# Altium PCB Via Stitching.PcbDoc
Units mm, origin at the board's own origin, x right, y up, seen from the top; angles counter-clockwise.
Board outline 80.01 x 48.01 mm, 2 copper layers (Top Layer, Bottom Layer); 52 components, 54 nets, 192 pads, 149 vias.
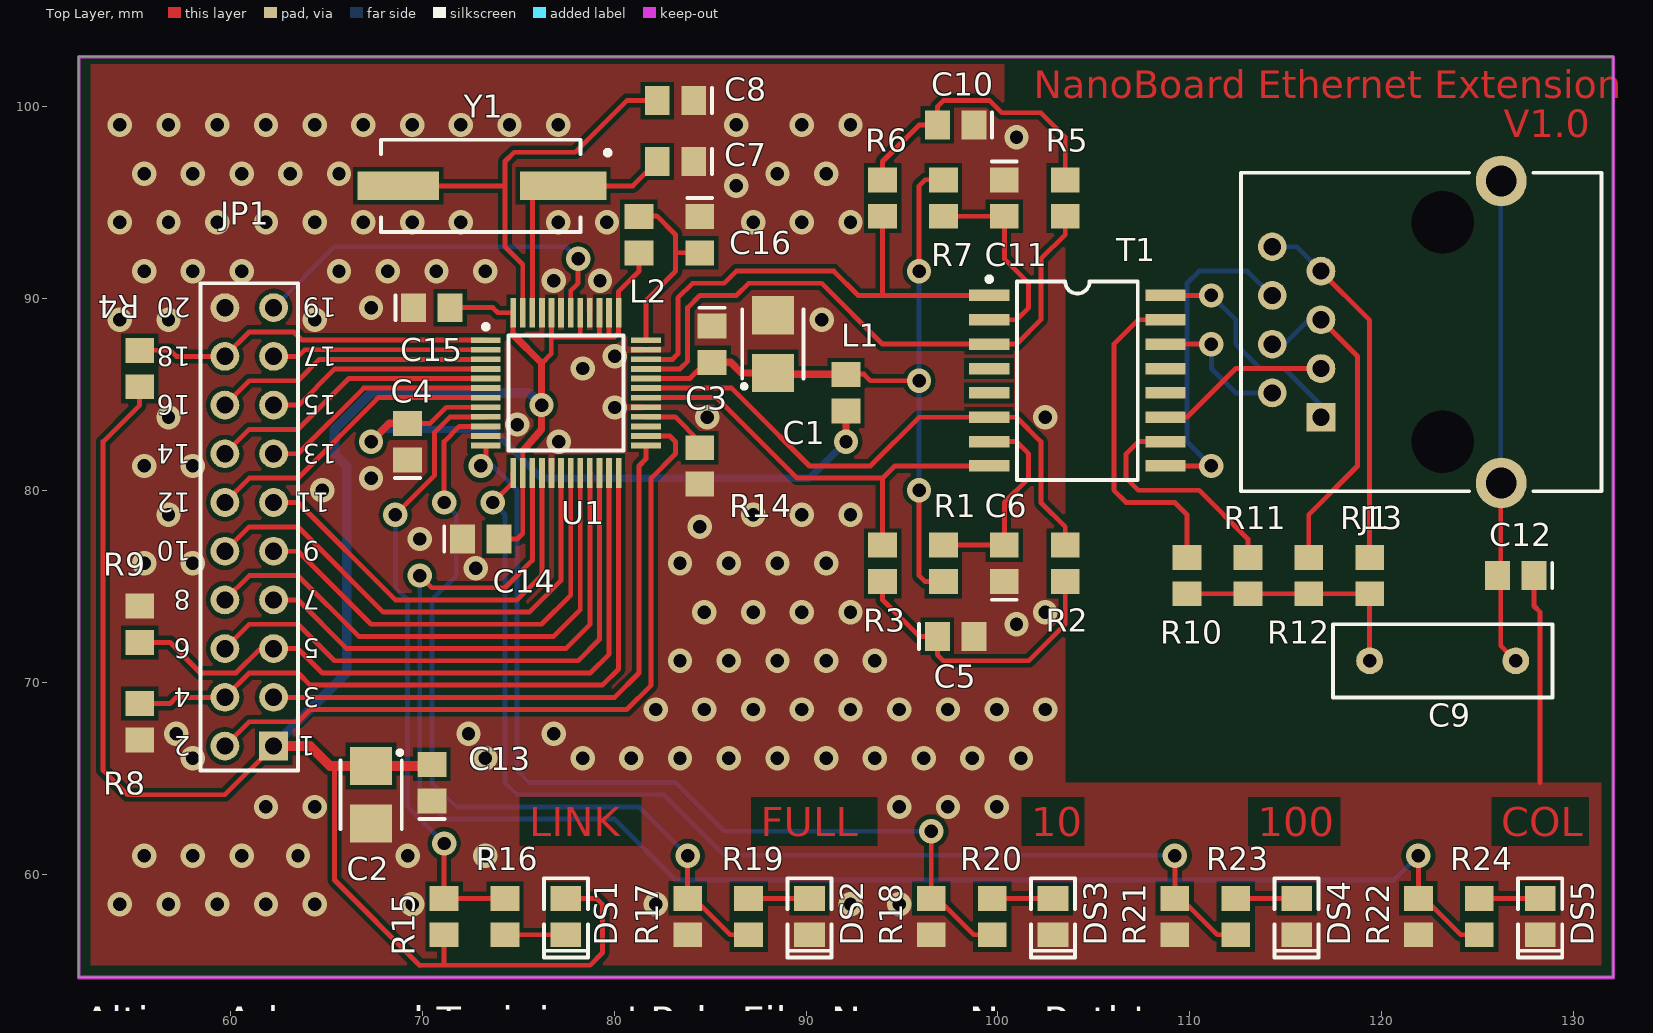
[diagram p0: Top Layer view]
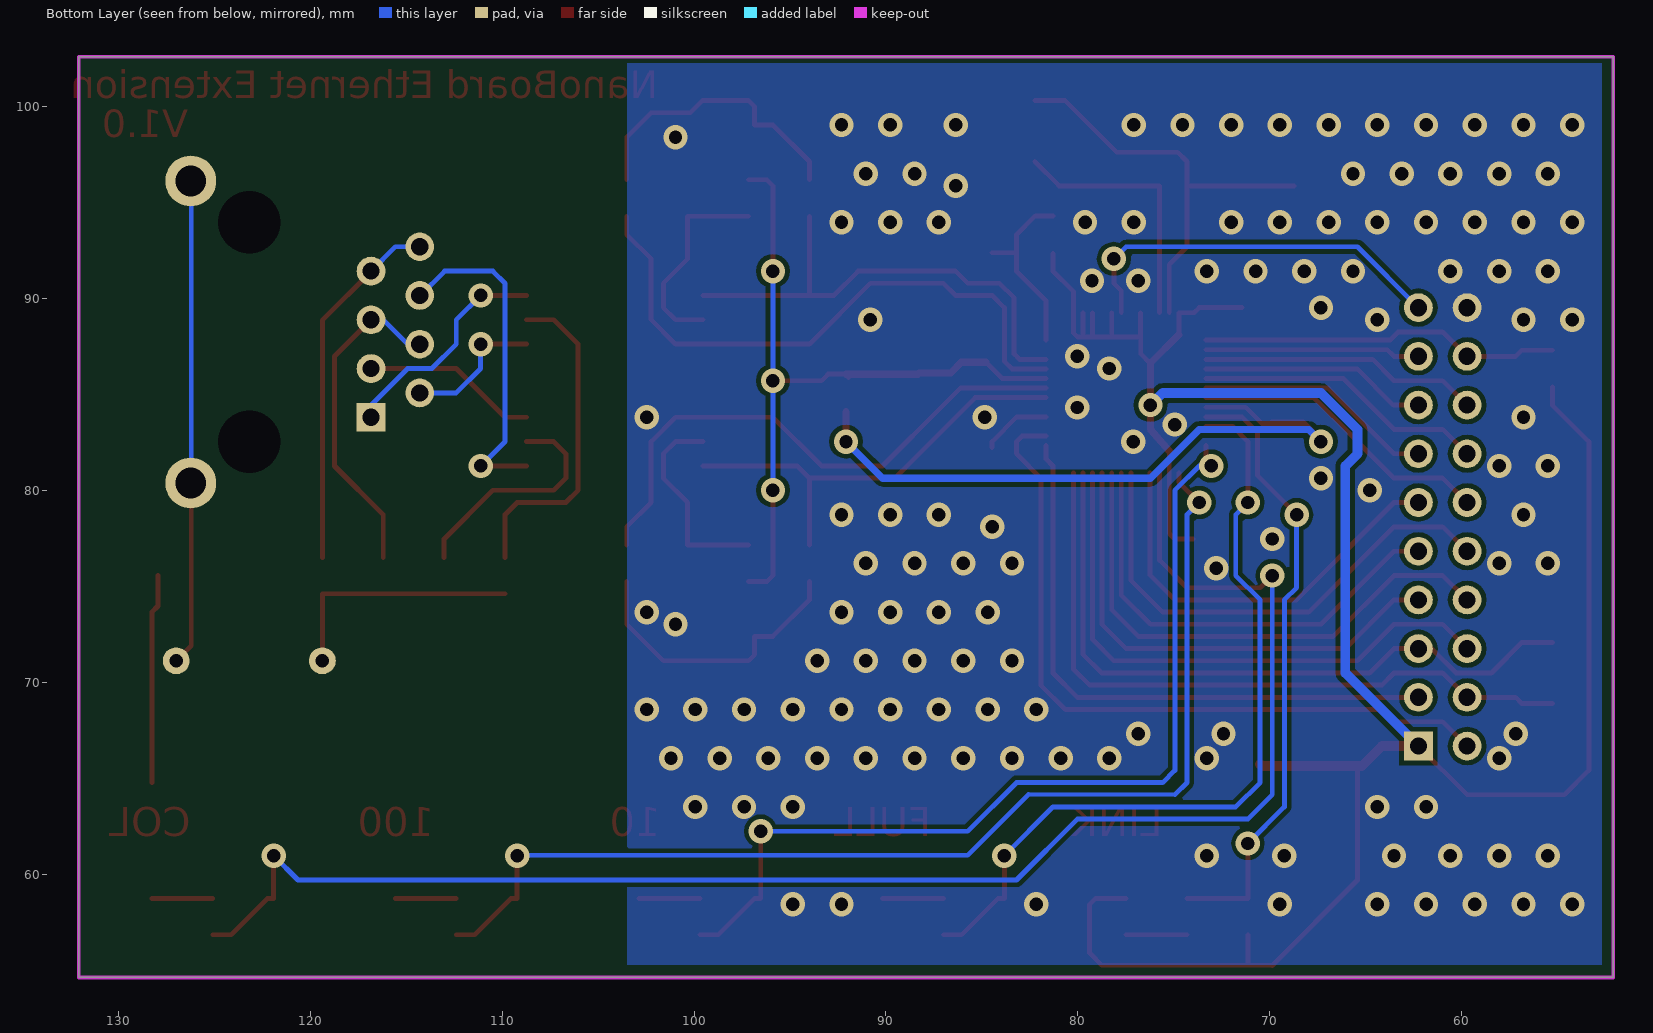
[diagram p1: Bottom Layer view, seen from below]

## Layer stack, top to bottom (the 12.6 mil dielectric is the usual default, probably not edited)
Top Solder: solder mask 0.0102, Solder Resist, Dk 3.5
Top Layer: signal copper 0.0356
Dielectric1: dielectric 0.32, FR-4, Dk 4.8
Bottom Layer: signal copper 0.0356
Bottom Solder: solder mask 0.0102, Solder Resist, Dk 3.5

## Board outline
52.07,54.61 52.07,102.616 132.08,102.616 132.08,54.61

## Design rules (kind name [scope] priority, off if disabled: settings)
Clearance Clearance_1 [(HasFootprint('TSQFP50P900X900-48'))] p1: gap=0.2 ignorepadtopadclearanceinfootprint=FALSE except(0: Arc-Hole Track-Hole SMDPad-Hole THPad-Hole Via-Hole Fill-Hole Poly-Hole Region-Hole Text-Hole)
Clearance [All] p2: gap=0.24 ignorepadtopadclearanceinfootprint=FALSE except(0: Arc-Hole Track-Hole SMDPad-Hole THPad-Hole Via-Hole Fill-Hole Poly-Hole Region-Hole Text-Hole)
FabricationTestPointUsage TestPointUsage [All] p1 off: valid=0 allowmultiple=FALSE
FabricationTestpoint Testpoint [All] p1 off: side=3 testpointundercomponent=TRUE minsize=1.016 maxsize=2.54 preferedsize=1.524 minholesize=0 maxholesize=1.016 preferedholesize=0.813 testpointgrid=0.025 allowsidetop=TRUE allowsidebottom=TRUE usegrid=TRUE gridtolerance=0
HoleSize [All] p1: absolutevalues=TRUE maxlimit=3.5 minlimit=0.025 maxpercent=80.000 minpercent=20.000
PolygonConnect [All] p1: connectstyle=Direct reliefconductorwidth=0.254 reliefentries=4 polygonreliefangle="90 Angle" airgapwidth=0.254
RoomDefinition PHY [InComponentClass('PHY')] p1: confinementstyle=ConfineIn formatcopy=TRUE lockcomponents=FALSE outline 52.07,54.61 132.08,54.61 132.08,102.87 52.07,102.87
RoutingVias [All] p1: holewidth=0.7 width=1.27 viastyle="Through Hole" minholewidth=0.7 minwidth=1.27 maxholewidth=0.7 maxwidth=1.27
SilkToSolderMaskClearance SilkscreenOverComponentPads [IsPad] p1: minsilkscreentomaskgap=0.254 clearancetoexposedcopper=TRUE
SolderMaskExpansion [All] p1: expansion=0.102 istentingtop=FALSE
Width Width_1 [(InNet('3V3') OR InNet('GND') OR InNet('PWFBIN') OR InNet('PWFBOUT'))] p1: maxlimit=0.508 minlimit=0.127 preferedwidth=0.254
Width [All] p2: maxlimit=0.254 minlimit=0.254 preferedwidth=0.254
26 further rules are at their usual default settings.

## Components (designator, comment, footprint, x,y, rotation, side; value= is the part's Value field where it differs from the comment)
C1 "22uF 10V" CAPC3528 88.265,87.63 r90 top
C2 "22uF 10V" CAPC3528 67.31,64.135 r270 top
C3 "100nF 50V" CAPC2012 85.09,87.63 r270 top
C4 "100nF 50V" CAPC2012 69.215,82.55 r90 top
C5 "100nF 50V" CAPC2012 97.79,72.39 r0 top
C6 "100nF 50V" CAPC2012 100.33,76.2 r90 top
C7 "20pF 50V" CAPC2012 83.185,97.155 r180 top
C8 "20pF 50V" CAPC2012 83.185,100.33 r180 top
C9 "100pF 3KV" CAPR7_5-3_6x7_5 123.19,71.12 r0 top
C10 "100nF 50V" CAPC2012 97.79,99.06 r180 top
C11 "100nF 50V" CAPC2012 100.33,95.25 r270 top
C12 "100nF 50V" CAPC2012 127,75.565 r180 top
C13 "100nF 50V" CAPC2012 70.485,64.77 r90 top
C14 "100nF 50V" CAPC2012 73.025,77.47 r0 top
C15 "100nF 50V" CAPC2012 70.485,89.535 r0 top
C16 "100nF 50V" CAPC2012 84.455,93.345 r270 top
DS1 "RED" LED2013 77.47,57.785 r90 top
DS2 "RED" LED2013 90.17,57.785 r90 top
DS3 "RED" LED2013 102.87,57.785 r90 top
DS4 "RED" LED2013 115.57,57.785 r90 top
DS5 "RED" LED2013 128.27,57.785 r90 top
J1 "RJ45 HEADER" 95122-2881 120.27,88.265 r90 top
JP1 "2x10 HEADER" HDR2X10 62.23,66.675 r90 top
L1 "30R@100MHz 600mA" INDC2012 92.075,85.09 r270 top
L2 "30R@100MHz 600mA" INDC2012 81.28,93.345 r90 top
R1 "0R 5%" RESC2012 97.155,76.2 r270 top
R2 "50R 1%" RESC2012 103.505,76.2 r270 top
R3 "50R 1%" RESC2012 93.98,76.2 r270 top
R4 "5K1 5%" RESC2012 55.245,86.36 r270 top
R5 "50R 1%" RESC2012 103.505,95.25 r270 top
R6 "50R 1%" RESC2012 93.98,95.25 r270 top
R7 "0R 5%" RESC2012 97.155,95.25 r90 top
R8 "5K1 5%" RESC2012 55.245,67.945 r90 top
R9 "5K1 5%" RESC2012 55.245,73.025 r270 top
R10 "75R 5%" RESC2012 109.855,75.565 r90 top
R11 "75R 5%" RESC2012 113.03,75.565 r90 top
R12 "75R 5%" RESC2012 116.205,75.565 r90 top
R13 "75R 5%" RESC2012 119.38,75.565 r90 top
R14 "2K 1%" RESC2012 84.455,81.28 r90 top
R15 "5K1 5%" RESC2012 71.12,57.785 r270 top
R16 "510R 5%" RESC2012 74.295,57.785 r270 top
R17 "5K1 5%" RESC2012 83.82,57.785 r90 top
R18 "5K1 5%" RESC2012 96.52,57.785 r270 top
R19 "510R 5%" RESC2012 86.995,57.785 r90 top
R20 "510R 5%" RESC2012 99.695,57.785 r90 top
R21 "5K1 5%" RESC2012 109.22,57.785 r90 top
R22 "5K1 5%" RESC2012 121.92,57.785 r270 top
R23 "510R 5%" RESC2012 112.395,57.785 r90 top
R24 "510R 5%" RESC2012 125.095,57.785 r90 top
T1 "TS6121C" SOIC127P910-16 104.14,85.725 r270 top
U1 "RTL8201CL" TSQFP50P900X900-48 77.47,85.09 r0 top
Y1 "25MHz" "XTAL_HC49SMD 20Mhz  +/-30ppm 20pf" 73.025,95.885 r180 top

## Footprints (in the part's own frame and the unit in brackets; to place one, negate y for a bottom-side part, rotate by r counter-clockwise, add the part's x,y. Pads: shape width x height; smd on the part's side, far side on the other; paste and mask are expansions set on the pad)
95122-2881 [mm]
  rect 1.5x1.5 hole 0.9: 1(-4.445,3.43)
  round 1.5 hole 0.9: 2(-3.175,5.97) 3(-1.905,3.43) 4(-0.635,5.97) 5(0.635,3.43) 6(1.905,5.97) 7(3.175,3.43) 8(4.445,5.97)
  round 2.65 hole 1.6: MH1(-7.875,-5.97) MH2(7.875,-5.97)
  round 2.95 hole 3.25 unplated: MH3(-5.715,-2.92) MH4(5.715,-2.92)
  silkscreen extent -8.3,-11.2 8.3,7.6
CAPC2012 [mm]
  rect 1.3x1.5 smd: 1(-0.95,0) 2(0.95,0)
  silkscreen extent -1.9,-0.65 -1.9,0.65
CAPC3528 [mm]
  rect 2x2.2 smd: 1(-1.5,0) 2(1.5,0)
  silkscreen extent -2.3,-1.6 1.8,1.6
CAPR7_5-3_6x7_5 [mm]
  round 1.4 hole 0.7: 1(-3.81,0) 2(3.81,0)
  silkscreen extent -5.71,-1.91 5.71,1.91
HDR2X10 [mm]
  rect 1.5x1.5 hole 0.9: 1(0,0)
  round 1.5 hole 0.9: 2(0,2.54) 3(2.54,0) 4(2.54,2.54) 5(5.08,0) 6(5.08,2.54) 7(7.62,0) 8(7.62,2.54) 9(10.16,0) 10(10.16,2.54) 11(12.7,0) 12(12.7,2.54) 13(15.24,0) 14(15.24,2.54) 15(17.78,0) 16(17.78,2.54) 17(20.32,0) 18(20.32,2.54) 19(22.86,0) 20(22.86,2.54)
  silkscreen extent -1.27,-1.27 24.13,3.81, body extent -1.37,-1.37 24.23,3.91, height 3.2
INDC2012 [mm]
  rect 1.3x1.5 smd: 1(-0.95,0) 2(0.95,0)
LED2013 [mm]
  rect 1.3x1.6 smd: 1(0.95,0) 2(-0.95,0)
  silkscreen extent -2.13,-1.15 2,1.15
RESC2012 [mm]
  rect 1.3x1.5 smd: 1(-0.95,0) 2(0.95,0)
SOIC127P910-16 [mm]
  rect 0.6x2.1 smd: 1(-4.445,-4.6) 2(-3.175,-4.6) 3(-1.905,-4.6) 4(-0.635,-4.6) 5(0.635,-4.6) 6(1.905,-4.6) 7(3.175,-4.6) 8(4.445,-4.6) 9(4.445,4.6) 10(3.175,4.6) 11(1.905,4.6) 12(0.635,4.6) 13(-0.635,4.6) 14(-1.905,4.6) 15(-3.175,4.6) 16(-4.445,4.6)
  silkscreen extent -5.42,-4.72 5.17,3.15
TSQFP50P900X900-48 [mm]
  rect 1.55x0.3 smd: 1(-4.175,2.75) 2(-4.175,2.25) 3(-4.175,1.75) 4(-4.175,1.25) 5(-4.175,0.75) 6(-4.175,0.25) 7(-4.175,-0.25) 8(-4.175,-0.75) 9(-4.175,-1.25) 10(-4.175,-1.75) 11(-4.175,-2.25) 12(-4.175,-2.75) 25(4.175,-2.75) 26(4.175,-2.25) 27(4.175,-1.75) 28(4.175,-1.25) 29(4.175,-0.75) 30(4.175,-0.25) 31(4.175,0.25) 32(4.175,0.75) 33(4.175,1.25) 34(4.175,1.75) 35(4.175,2.25) 36(4.175,2.75)
  rect 0.3x1.55 smd: 13(-2.75,-4.175) 14(-2.25,-4.175) 15(-1.75,-4.175) 16(-1.25,-4.175) 17(-0.75,-4.175) 18(-0.25,-4.175) 19(0.25,-4.175) 20(0.75,-4.175) 21(1.25,-4.175) 22(1.75,-4.175) 23(2.25,-4.175) 24(2.75,-4.175) 37(2.75,4.175) 38(2.25,4.175) 39(1.75,4.175) 40(1.25,4.175) 41(0.75,4.175) 42(0.25,4.175) 43(-0.25,4.175) 44(-0.75,4.175) 45(-1.25,4.175) 46(-1.75,4.175) 47(-2.25,4.175) 48(-2.75,4.175)
  silkscreen extent -4.3,-3 3,3.57, body extent -3,-3 3,3, height 1.7
"XTAL_HC49SMD 20Mhz  +/-30ppm 20pf" [mm]
  rect 4.5x1.5 smd: 1(-4.3,0)
  rect 4.25x1.5 smd: 2(4.3,0)
  silkscreen extent -6.75,-2.4 5.2,2.4

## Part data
C1 C2: library part "Cap Pol1", "Polarized Capacitor (Radial)"
C3 C4 C5 C6 C7 C8 C9 C10 C11 C12 C13 C14 C15 C16: library part Cap, "Capacitor"
DS1 DS2 DS3 DS4 DS5: library part LED3, "Fairchild LED RED"
J1: library part 95122-2881, "Right Angle, Standard Profile, External Shield PCB Jack"
JP1: library part "Header 10X2", "Header, 10-Pin, Dual row"
L1 L2: library part Inductor, "Inductor Ferroxcube"
R1 R2 R3 R4 R5 R6 R7 R8 R9 R10 R11 R12 R13 R14 R15 R16 R17 R18 R19 R20 R21 R22 R23 R24: library part Res2, "Resistor"
T1: "Bothhand 10/100 BaseT Pulse Transformer"
U1: "Realtek Ethernet PHY tranceiver"
Y1: library part XTAL, "Crystal Oscillator"

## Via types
v1: diameter 1.27, hole 0.7, Top Layer to Bottom Layer, 149 vias

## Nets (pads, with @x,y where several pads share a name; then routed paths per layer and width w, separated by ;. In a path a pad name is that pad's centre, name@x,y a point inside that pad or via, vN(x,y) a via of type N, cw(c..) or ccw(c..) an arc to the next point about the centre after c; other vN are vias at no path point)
3V3: C2.1 C13.2 C14.2 C15.2 DS1.1 JP1.1 L2.1 R4.2 R15.2 U1.14 U1.37 U1.38 U1.39 U1.41 U1.44 U1.48 | length 130.3
  Top Layer w0.254: R4.2 55.245,84.455 53.34,82.55 53.34,65.405 54.61,64.135 59.69,64.135 JP1.1 ; 65.405,65.635 65.405,59.69 69.85,55.235 78.74,55.245 79.37,55.885 79.37,58.42 79.055,58.735 DS1.1 ; 71.12,55.255 R15.2 ; C15.2 73.66,89.535 73.93,89.265 U1.48 74.72,88.124 ; C14.2 74.93,77.47 75.22,77.76 U1.14 75.22,82.056 ; 76.2,86.614 76.708,87.122 76.708,88.011 80.01,88.011 80.22,88.221 80.22,90.38 81.28,91.44 L2.1@81.28,92.37 ; 76.72,88.023 U1.44 ; 78.22,88.023 U1.41 ; 79.22,88.039 U1.39 ; 79.72,88.047 U1.38
  Top Layer w0.381: 74.72,88.124 76.2,86.644 76.2,83.185 75.22,82.056
  Top Layer w0.508: JP1.1 64.135,66.675 65.175,65.635 70.4,65.635 C13.2
  Bottom Layer w0.508: JP1.1 66.04,70.485 66.04,81.28 65.405,81.915 65.405,83.185 67.31,85.09 75.565,85.09 v1(76.2,84.455)
3V3A: C16.2 L2.2 U1.36 | length 9.7
  Top Layer w0.254: L2.2@81.28,94.32 82.21,94.32 83.185,93.345 83.185,91.44 81.645,89.9 U1.36 ; 83.19,92.395 C16.2
COL: JP1.18 R4.1 U1.1 | length 18.9
  Top Layer w0.254: R4.1@55.245,87.315 56.83,87.315 57.15,86.995 JP1.18 60.96,88.265 63.285,88.265 63.71,87.84 U1.1
CRS: JP1.5 R9.2 U1.23 | length 36
  Top Layer w0.254: R9.2 56.83,72.075 58.42,70.485 60.261,70.485 61.531,71.755 JP1.5 63.5,71.755 64.77,70.485 78.74,70.485 79.72,71.465 U1.23
GND: C1.2 C2.2 C3.1 C4.1 C5.2 C6.1 C7.1 C8.1 C10.1 C11.1 C12.1 C13.1 C14.1 C15.1 C16.1 DS2.2 DS3.2 DS4.2 DS5.2 JP1.20 R8.1 R9.1 R14.1 R17.1 R18.2 R21.1 R22.2 U1.11 U1.17 U1.29 U1.35 U1.40 U1.43 U1.45 | length 10.9
  Top Layer w0.254: C12.1 127.95,73.98 128.27,73.66 128.27,64.77
  other v1: 54.21,58.42 56.75,58.42 59.29,58.42 61.83,58.42 64.37,58.42 69.45,58.42 82.15,58.42 92.31,58.42 94.85,58.42 55.48,60.96 58.02,60.96 60.56,60.96 63.5,60.96 69.215,60.96 73.26,60.96 61.83,63.5 64.37,63.5 94.85,63.5 97.39,63.5 99.93,63.5 58.02,66.04 73.26,66.04 78.34,66.04 80.88,66.04 83.42,66.04 85.96,66.04 88.5,66.04 91.04,66.04 93.58,66.04 96.12,66.04 98.66,66.04 101.2,66.04 57.15,67.31 72.39,67.31 76.835,67.31 82.15,68.58 84.69,68.58 87.23,68.58 89.77,68.58 92.31,68.58 94.85,68.58 97.39,68.58 99.93,68.58 102.47,68.58 83.42,71.12 85.96,71.12 88.5,71.12 91.04,71.12 93.58,71.12 100.965,73.025 84.69,73.66 87.23,73.66 89.77,73.66 92.31,73.66 102.47,73.66 72.771,75.946 55.48,76.2 58.02,76.2 83.42,76.2 85.96,76.2 88.5,76.2 91.04,76.2 69.85,77.47 84.455,78.105 56.75,78.74 87.23,78.74 89.77,78.74 92.31,78.74 64.77,80.01 67.31,80.645 55.48,81.28 58.02,81.28 77.089,82.55 74.93,83.439 56.75,83.82 84.836,83.82 102.47,83.82 80.01,84.328 78.34,86.36 80.01,86.995 54.21,88.9 56.75,88.9 64.37,88.9 90.805,88.9 67.31,89.535 76.835,90.932 79.248,90.932 55.48,91.44 58.02,91.44 60.56,91.44 65.64,91.44 68.18,91.44 70.72,91.44 73.26,91.44 54.21,93.98 56.75,93.98 59.29,93.98 61.83,93.98 64.37,93.98 66.91,93.98 69.45,93.98 71.99,93.98 77.07,93.98 79.61,93.98 87.23,93.98 89.77,93.98 92.31,93.98 86.36,95.885 55.48,96.52 58.02,96.52 60.56,96.52 63.1,96.52 65.64,96.52 88.5,96.52 91.04,96.52 100.965,98.425 54.21,99.06 56.75,99.06 59.29,99.06 61.83,99.06 64.37,99.06 66.91,99.06 69.45,99.06 71.99,99.06 74.53,99.06 77.07,99.06 86.36,99.06 89.77,99.06 92.31,99.06
LED0: R15.1 R16.1 U1.9 | length 32.4
  Top Layer w0.254: v1(68.58,78.74) 70.628,80.788 70.628,83.034 71.434,83.84 U1.9 ; v1(71.12,61.595) R15.1 R16.1
  Bottom Layer w0.254: v1(68.58,78.74) 68.58,74.93 69.215,74.295 69.215,63.5 v1(71.12,61.595)
LED1: R17.2 R19.1 U1.10 | length 42.2
  Top Layer w0.254: v1@71.122,79.377 71.122,82.552 71.91,83.34 U1.10 ; v1(83.82,60.96) R17.2 84.14,58.735 86.04,56.835 R19.1
  Bottom Layer w0.254: v1(71.12,79.375) 71.755,78.74 71.755,75.565 70.485,74.295 70.485,64.77 71.755,63.5 81.28,63.5 v1(83.82,60.96)
LED2: R18.1 R20.1 U1.12 | length 48.6
  Top Layer w0.254: v1(73.025,81.28) 73.295,81.55 U1.12 ; v1(96.52,62.23) R18.1 96.835,58.735 98.735,56.835 R20.1
  Bottom Layer w0.254: v1(73.025,81.28) 73.66,81.28 74.93,80.01 74.93,65.405 75.565,64.77 83.185,64.77 85.725,62.23 v1(96.52,62.23)
LED3: R21.2 R23.1 U1.13 | length 59.5
  Top Layer w0.254: v1(73.66,79.375) 74.72,80.435 U1.13 ; v1(109.22,60.96) R21.2 109.54,58.735 111.44,56.835 R23.1
  Bottom Layer w0.254: v1(73.66,79.375) 74.295,78.74 74.295,64.77 74.93,64.135 82.55,64.163 85.725,60.988 v1(109.22,60.96)
LED4: R22.1 R24.1 U1.15 | length 83.3
  Top Layer w0.254: v1(69.85,75.565) 70.485,74.93 74.295,74.93 75.72,76.355 U1.15 ; v1(121.92,60.96) R22.1 122.235,58.735 124.135,56.835 R24.1
  Bottom Layer w0.254: v1(69.85,75.565) 69.85,64.135 71.12,62.865 80.01,62.865 83.185,59.69 120.65,59.69 v1(121.92,60.96)
MDC: JP1.3 U1.25 | length 31.6
  Top Layer w0.254: JP1.3 80.01,69.215 81.28,70.485 81.28,81.28 81.645,81.645 U1.25
MDIO: JP1.2 U1.26 | length 38.4
  Top Layer w0.254: JP1.2 60.96,67.945 63.5,67.945 64.135,68.58 80.645,68.58 81.915,69.85 81.915,80.645 83.185,81.915 83.185,82.55 82.895,82.84 U1.26
NetC5_1: C5.1 R2.2 R3.2 | length 15.4
  Top Layer w0.254: R3.2 93.98,74.295 95.885,72.39 C5.1 96.84,71.435 97.155,71.12 101.6,71.12 103.505,73.025 R2.2
NetC6_2: C6.2 R1.1 T1.7 | length 10.8
  Top Layer w0.254: R1.1 C6.2 100.33,79.375 101.6,80.645 101.6,81.915 100.965,82.55 T1.7
NetC7_2: C7.2 U1.46 Y1.1 | length 13.7
  Top Layer w0.254: U1.46 75.72,95.885 80.965,95.885 C7.2
NetC8_2: C8.2 U1.47 Y1.2 | length 23.1
  Top Layer w0.254: Y1.2 74.295,95.885 ; U1.47 75.22,91.785 74.295,92.71 74.295,97.155 74.775,97.635 77.95,97.635 80.645,100.33 C8.2
NetC9_1: C9.1 R10.1 R11.1 R12.1 R13.1 | length 13
  Top Layer w0.254: R10.1 R13.1 C9.1
NetC9_2: C9.2 C12.2 J1.MH1 J1.MH2 | length 25.3
  Top Layer w0.254: J1.MH1@126.215,80.39 126.215,71.905 C9.2
  Bottom Layer w0.254: J1.MH1@126.215,80.39 J1.MH2@126.215,96.14
NetC10_2: C10.2 R5.1 R6.1 | length 15.4
  Top Layer w0.254: R6.1 93.98,97.155 95.885,99.06 C10.2 96.84,100.015 97.155,100.33 99.568,100.33 100.203,99.695 102.235,99.695 103.505,98.425 R5.1
NetC11_2: C11.2 R7.1 T1.2 | length 10.8
  Top Layer w0.254: R7.1 C11.2 100.33,92.075 101.6,90.805 101.6,89.535 100.965,88.9 T1.2
NetDS1_2: DS1.2 R16.2 | length 3.2
  Top Layer w0.254: R16.2 DS1.2
NetDS2_1: DS2.1 R19.2 | length 3.2
  Top Layer w0.254: R19.2 DS2.1
NetDS3_1: DS3.1 R20.2 | length 3.2
  Top Layer w0.254: R20.2 DS3.1
NetDS4_1: DS4.1 R23.2 | length 3.2
  Top Layer w0.254: R23.2 DS4.1
NetDS5_1: DS5.1 R24.2 | length 3.2
  Top Layer w0.254: R24.2 DS5.1
NetJ1_1: J1.1 T1.16 | length 11.8
  Top Layer w0.254: T1.16 v1(111.125,90.17)
  Bottom Layer w0.254: v1(111.125,90.17) 112.395,88.9 112.395,87.63 113.665,86.36 114.935,86.36 116.815,84.48 J1.1@116.815,83.82
NetJ1_2: J1.2 T1.14 | length 7.3
  Top Layer w0.254: T1.14 v1(111.125,87.63)
  Bottom Layer w0.254: v1(111.125,87.63) 111.125,86.36 112.395,85.09 J1.2@114.275,85.09
NetJ1_3: J1.3 T1.11 | length 9.1
  Top Layer w0.254: T1.11 109.855,83.82 112.395,86.36 J1.3@116.815,86.36
NetJ1_4: J1.4 J1.5 R12.2 | length 16.7
  Top Layer w0.254: R12.2 116.205,78.74 118.745,81.28 118.745,86.995 J1.5
  Bottom Layer w0.254: J1.4@114.275,87.63 114.935,87.63 J1.5@116.205,88.9
NetJ1_6: J1.6 T1.9 | length 17.6
  Top Layer w0.254: T1.9 v1(111.125,81.28)
  Bottom Layer w0.254: v1(111.125,81.28) 109.855,82.55 109.855,90.805 110.49,91.44 113.005,91.44 J1.6@114.275,90.17
NetJ1_7: J1.7 J1.8 R13.2 | length 19
  Top Layer w0.254: J1.7@116.815,91.44 119.38,88.875 R13.2
  Bottom Layer w0.254: J1.8@114.275,92.71 115.57,92.71 J1.7@116.815,91.465
NetR2_1: R2.1 T1.6 U1.31 | length 29.8
  Top Layer w0.254: U1.31 86.11,85.34 86.995,84.455 90.17,81.28 93.345,81.28 95.885,83.82 T1.6 100.965,83.82 102.235,82.55 102.235,79.375 103.505,78.105 R2.1
NetR3_1: R3.1 T1.8 U1.30 | length 23.4
  Top Layer w0.254: U1.30 85.34,84.84 89.535,80.645 93.98,80.645 ; R3.1 93.98,80.645 ; T1.8 94.615,81.28 93.98,80.645
NetR5_2: R5.2 T1.3 U1.33 | length 31.8
  Top Layer w0.254: U1.33 83.419,86.34 83.82,86.741 83.82,89.535 84.455,90.17 86.36,90.17 86.995,90.805 90.805,90.805 93.98,87.63 T1.3 100.965,87.63 102.235,88.9 102.235,92.075 103.505,93.345 R5.2
NetR6_2: R6.2 T1.1 U1.34 | length 26.2
  Top Layer w0.254: U1.34 83.03,86.84 83.312,87.122 83.312,90.043 84.074,90.805 85.725,90.805 86.36,91.44 91.44,91.44 92.71,90.17 T1.1 ; 93.98,90.17 R6.2
NetR10_2: R10.2 T1.15 | length 17.4
  Top Layer w0.254: T1.15 107.315,88.9 106.045,87.63 106.045,80.01 106.68,79.375 109.22,79.375 109.855,78.74 R10.2
NetR11_2: R11.2 T1.10 | length 12.2
  Top Layer w0.254: T1.10 107.315,82.55 106.68,81.915 106.68,80.645 107.315,80.01 110.49,80.01 113.03,77.47 R11.2
NetR14_2: R14.2 U1.28 | length 3.7
  Top Layer w0.254: U1.28 83.165,83.84 84.455,82.55 R14.2
PWFBIN: C4.2 L1.2 U1.8 | length 35.2
  Top Layer w0.254: C4.2@69.85,83.5 70.395,83.5 71.235,84.34 U1.8
  Top Layer w0.381: v1(67.31,82.55) 68.26,83.5 C4.2@69.85,83.5 ; v1(92.075,82.55) L1.2@92.075,84.115
  Bottom Layer w0.381: v1(67.31,82.55) 67.945,83.185 73.66,83.185 76.2,80.645 90.17,80.645 v1(92.075,82.55)
PWFBOUT: C1.1 C3.2 L1.1 R1.2 R7.2 U1.32 | length 38.1
  Top Layer w0.254: U1.32 83.935,85.84 C3.2@84.775,86.68 ; C1.1 C1.1@88.33,86.065 ; L1.1@91.931,85.876 L1.1@91.948,85.893 ; L1.1@92.075,86.065 93.005,86.065 93.345,85.725 v1(95.885,85.725) ; v1(95.885,80.01) 95.885,75.565 96.2,75.25 R1.2 ; v1(95.885,91.44) 95.885,95.885 96.2,96.2 R7.2
  Top Layer w0.381: C3.2@84.775,86.68 86.066,86.68 86.616,86.13 C1.1 ; C1.1@88.33,86.065 L1.1@92.075,86.065
  Bottom Layer w0.254: v1(95.885,80.01) v1(95.885,91.44)
RESETB: JP1.19 U1.42 | length 20.4
  Top Layer w0.254: U1.42 77.72,90.42 78.105,90.805 v1(78.105,92.075)
  Bottom Layer w0.254: JP1.19 65.405,92.71 77.47,92.71 v1(78.105,92.075)
RXC: JP1.11 U1.16 | length 22
  Top Layer w0.254: JP1.11 63.5,79.375 68.58,74.295 74.93,74.295 76.22,75.585 U1.16
RXD0: JP1.7 U1.21 | length 26
  Top Layer w0.254: JP1.7 63.5,74.295 66.04,71.755 77.47,71.755 78.72,73.005 U1.21
RXD1: JP1.8 U1.20 | length 28.1
  Top Layer w0.254: JP1.8 60.96,75.565 63.5,75.565 66.675,72.39 76.835,72.39 78.22,73.775 U1.20
RXD2: JP1.9 U1.19 | length 24.1
  Top Layer w0.254: JP1.9 63.5,76.835 67.31,73.025 76.2,73.025 77.72,74.545 U1.19
RXD3: JP1.10 U1.18 | length 26.2
  Top Layer w0.254: JP1.10 60.96,78.105 63.5,78.105 67.945,73.66 75.565,73.66 77.22,75.315 U1.18
RXDV: JP1.6 U1.22 | length 30
  Top Layer w0.254: JP1.6 60.96,73.025 63.5,73.025 65.405,71.12 78.105,71.12 79.22,72.235 U1.22
RXER: JP1.4 R8.2 U1.24 | length 36.5
  Top Layer w0.254: R8.2 56.835,68.895 57.155,69.215 JP1.4 60.96,70.485 63.5,70.485 64.135,69.85 79.375,69.85 80.22,70.695 U1.24
TXC: JP1.12 U1.7 | length 15.9
  Top Layer w0.254: JP1.12 60.96,80.645 63.5,80.645 67.695,84.84 U1.7
TXD0: JP1.13 U1.6 | length 12.5
  Top Layer w0.254: JP1.13 63.5,81.915 66.925,85.34 U1.6
TXD1: JP1.14 U1.5 | length 15.2
  Top Layer w0.254: JP1.14 60.96,83.185 63.5,83.185 66.155,85.84 U1.5
TXD2: JP1.15 U1.4 | length 11.8
  Top Layer w0.254: JP1.15 63.54,84.455 65.425,86.34 U1.4
TXD3: JP1.16 U1.3 | length 14.6
  Top Layer w0.254: JP1.16 60.96,85.725 63.5,85.725 64.615,86.84 U1.3
TXEN: JP1.17 U1.2 | length 11.2
  Top Layer w0.254: JP1.17 63.5,86.995 63.845,87.34 U1.2
pads on no net: J1.MH3 J1.MH4 T1.4 T1.5 T1.12 T1.13 U1.27

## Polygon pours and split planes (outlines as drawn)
GND on Top Layer "Top Layer-GND" (solid, remove dead copper, pour order 1000): 52.705,102.235 100.33,102.235 100.33,99.695 102.87,99.695 103.505,99.06 103.505,64.77 131.445,64.77 131.445,55.245 52.705,55.245
GND on Bottom Layer "Bottom Layer-GND" (solid, remove dead copper, pour order 1001): 52.68,102.27 103.48,102.27 103.48,55.28 52.68,55.28

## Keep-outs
Keep-Out Layer:
  the board outline again, w0.2

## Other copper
Top Layer:
  text "NanoBoard Ethernet Extension" at 101.854,100.457 h1.45
  text "V1.0" at 126.365,98.425 h1.45
  text "LINK" at 75.565,61.976 h1.52
  text "FULL" at 87.63,61.976 h1.52
  text "10" at 101.727,61.976 h1.52
  text "100" at 113.538,61.976 h1.52
  text "COL" at 126.238,61.976 h1.52

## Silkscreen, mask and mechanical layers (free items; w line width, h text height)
Top Overlay:
  text "Altium Advanced Training: '.Pcb_File_Name_No_Path'" at 52.324,51.562 h1.52
Mechanical 1:
  the board outline again, w0.2
Via Stitching Constraint Area:
  lines w0.5: 51.435,53.975 52.705,55.245 ; 51.435,103.505 52.705,102.235 ; 52.705,50.165 52.705,55.245 ; 52.705,107.315 52.705,102.235 ; 53.975,53.975 52.705,55.245 ; 53.975,103.505 52.705,102.235 ; 102.235,53.975 103.505,55.245 ; 102.235,103.505 103.505,102.235 ; 103.505,50.165 103.505,55.245 ; 103.505,107.315 103.505,102.235 ; 104.775,53.975 103.505,55.245 ; 104.775,103.505 103.505,102.235
  text "ViaStitching Constraint Area" at 58.42,104.14 h1.5

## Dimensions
52.07,102.616 to 52.07,54.61 on Mechanical 1
52.07,54.61 to 132.08,54.61 on Mechanical 1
